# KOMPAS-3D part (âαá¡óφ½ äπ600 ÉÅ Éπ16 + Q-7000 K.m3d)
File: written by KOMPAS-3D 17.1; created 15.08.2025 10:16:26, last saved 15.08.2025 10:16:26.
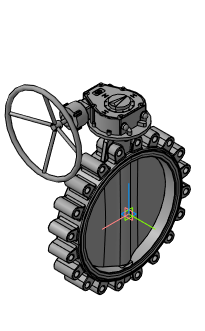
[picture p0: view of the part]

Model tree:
1. Операция без истории:1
